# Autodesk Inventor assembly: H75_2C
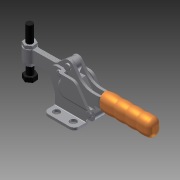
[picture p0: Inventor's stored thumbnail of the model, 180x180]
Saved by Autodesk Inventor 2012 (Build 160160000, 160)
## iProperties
Created: 2012-01
Part Number: H75_2C
Document SubType Name: Assembly
Designer: Shane
Author: Shane
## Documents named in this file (18)
- P:\SHANE(PUBLIC)\brauer clamps\H75_2C.iam
- P:\SHANE(PUBLIC)\brauer clamps\Imported Components\H75-2C-3D\Part2.ipt
- P:\SHANE(PUBLIC)\brauer clamps\Imported Components\H75-2C-3D\Part4.ipt
- P:\SHANE(PUBLIC)\brauer clamps\Imported Components\H75-2C-3D\Part6.ipt
- P:\SHANE(PUBLIC)\brauer clamps\Imported Components\H75-2C-3D\Part8.ipt
- P:\SHANE(PUBLIC)\brauer clamps\Imported Components\H75-2C-3D\Part10.ipt
- P:\SHANE(PUBLIC)\brauer clamps\Imported Components\H75-2C-3D\Part12.ipt
- P:\SHANE(PUBLIC)\brauer clamps\Imported Components\H75-2C-3D\Part14.ipt
- P:\SHANE(PUBLIC)\brauer clamps\Imported Components\H75-2C-3D\Part16.ipt
- P:\SHANE(PUBLIC)\brauer clamps\Imported Components\H75-2C-3D\Part18.ipt
- P:\SHANE(PUBLIC)\brauer clamps\Imported Components\H75-2C-3D\Part20.ipt
- P:\SHANE(PUBLIC)\brauer clamps\Imported Components\H75-2C-3D\Part22.ipt
- P:\SHANE(PUBLIC)\brauer clamps\Imported Components\H75-2C-3D\Part24.ipt
- P:\SHANE(PUBLIC)\brauer clamps\Imported Components\H75-2C-3D\Part26.ipt
- P:\SHANE(PUBLIC)\brauer clamps\Imported Components\H75-2C-3D\Part28.ipt
- P:\SHANE(PUBLIC)\brauer clamps\Imported Components\H75-2C-3D\Part30.ipt
- P:\SHANE(PUBLIC)\brauer clamps\Imported Components\H75-2C-3D\Part32.ipt
- P:\SHANE(PUBLIC)\brauer clamps\Imported Components\H75-2C-3D\Part34.ipt
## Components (17 placed, 17 different names)
1. Part2:1
2. Part4:1
3. Part6:1
4. Part8:1
5. Part10:1
6. Part12:1
7. Part14:1
8. Part16:1
9. Part18:1
10. Part20:1
11. Part22:1
12. Part24:1
13. Part26:1
14. Part28:1
15. Part30:1
16. Part32:1
17. Part34:1
